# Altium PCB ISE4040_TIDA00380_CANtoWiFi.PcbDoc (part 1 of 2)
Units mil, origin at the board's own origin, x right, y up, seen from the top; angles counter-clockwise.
Board outline 2700 x 3450 mil, 4 copper layers (Top Layer, Signal Layer 1, Signal Layer 2, Bottom Layer), stack 61.6 mil thick; 119 components, 58 nets, 367 pads, 332 vias.
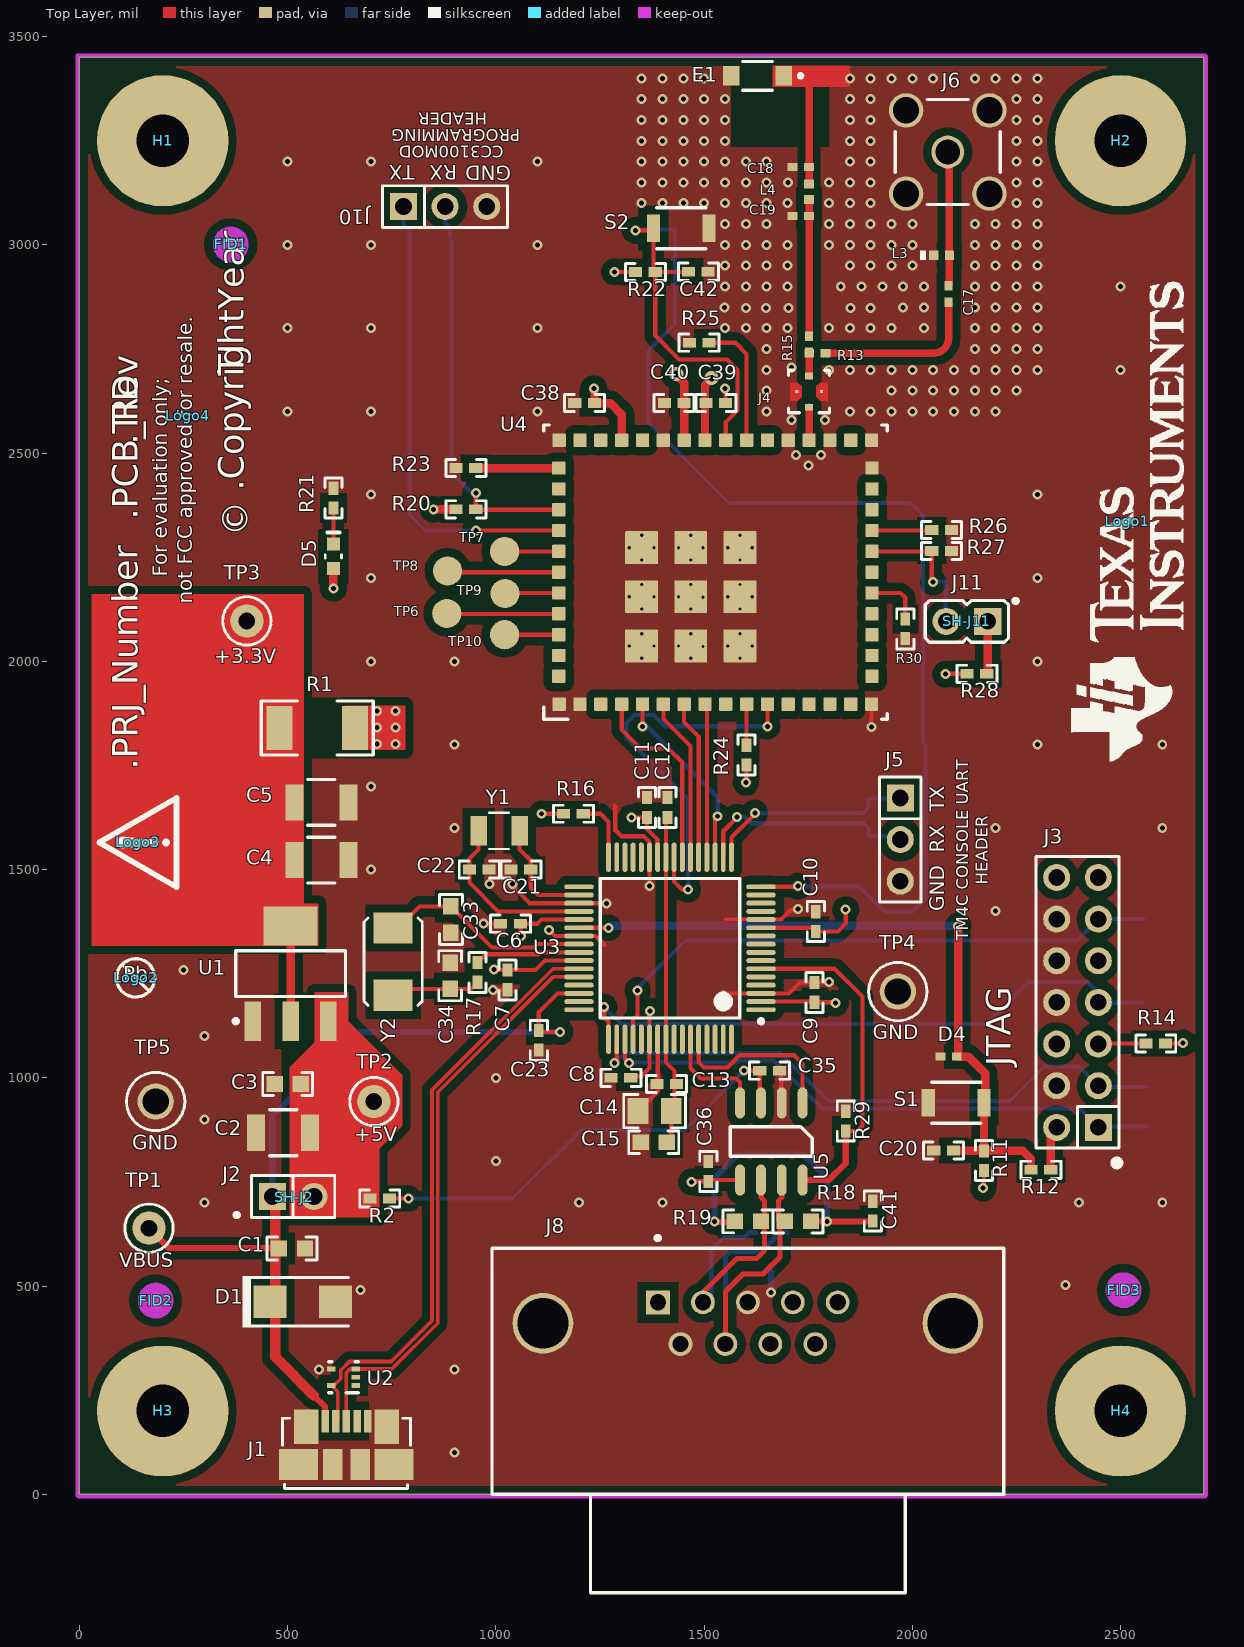
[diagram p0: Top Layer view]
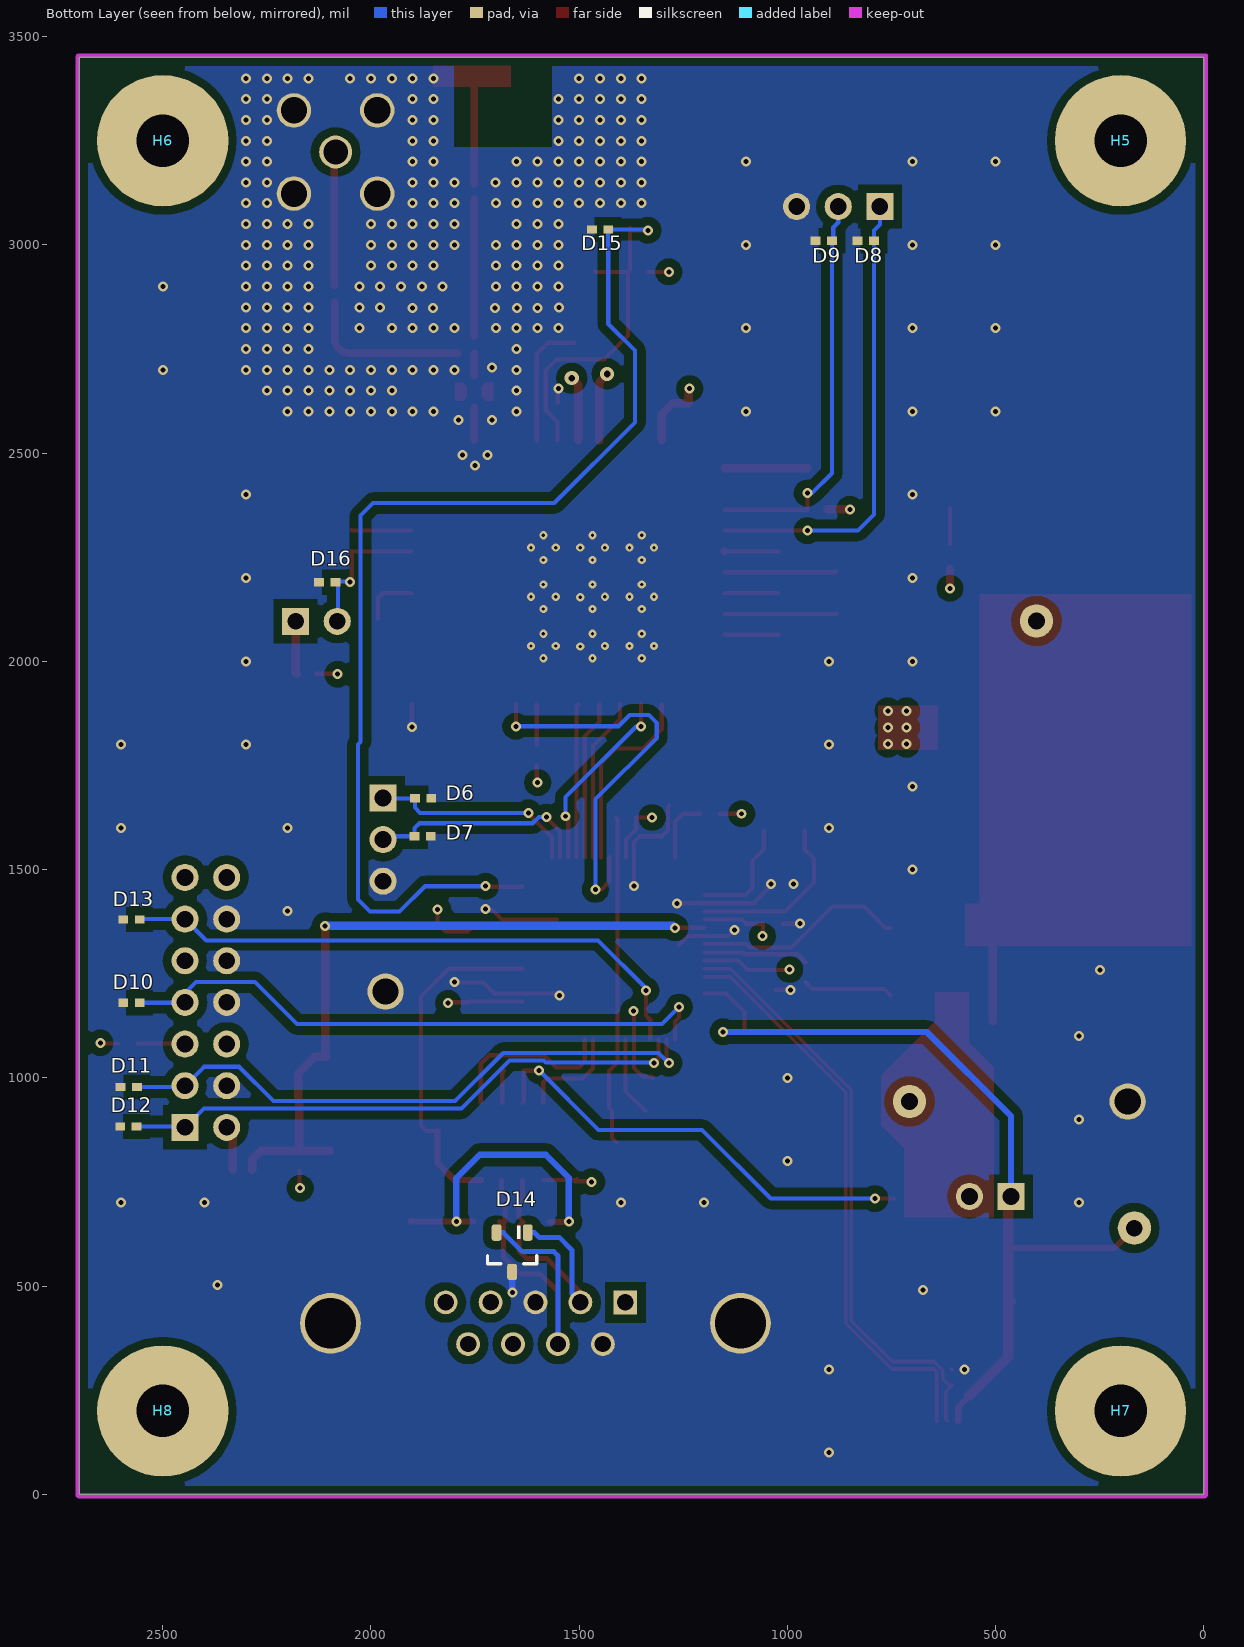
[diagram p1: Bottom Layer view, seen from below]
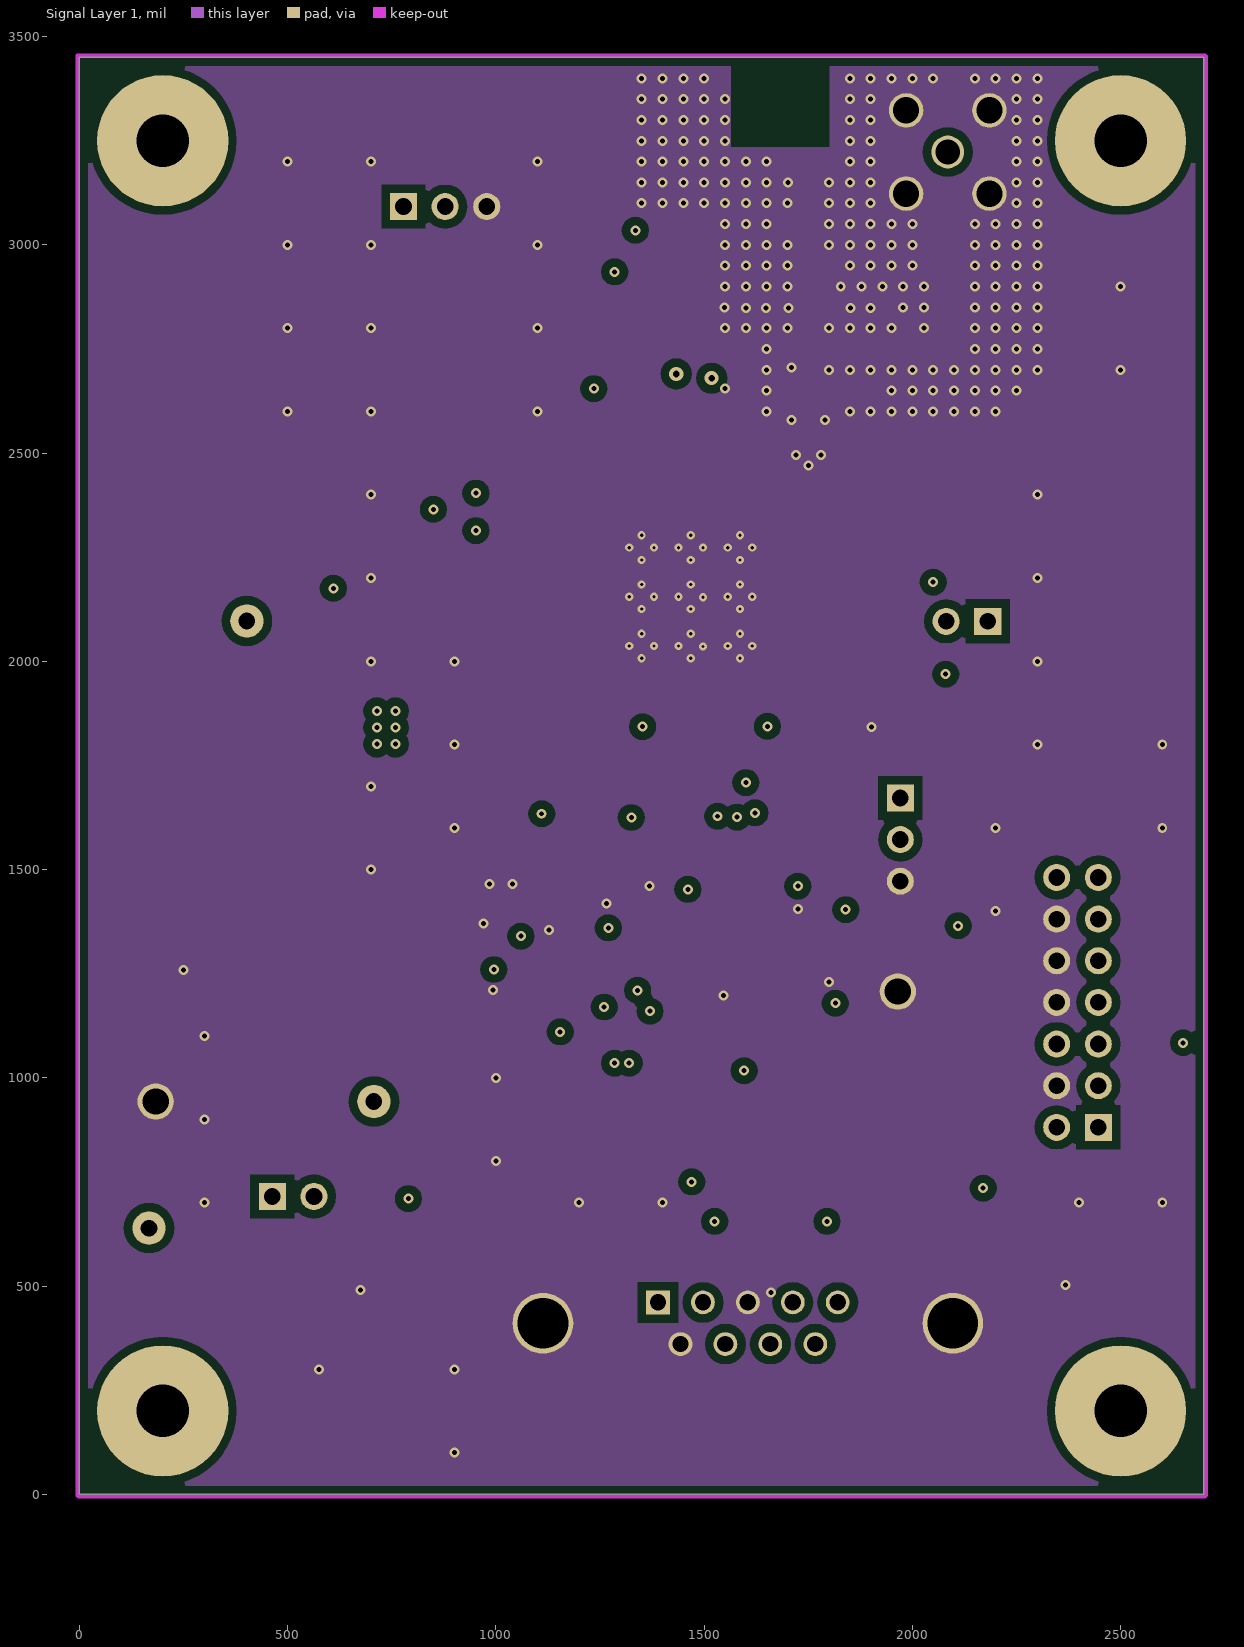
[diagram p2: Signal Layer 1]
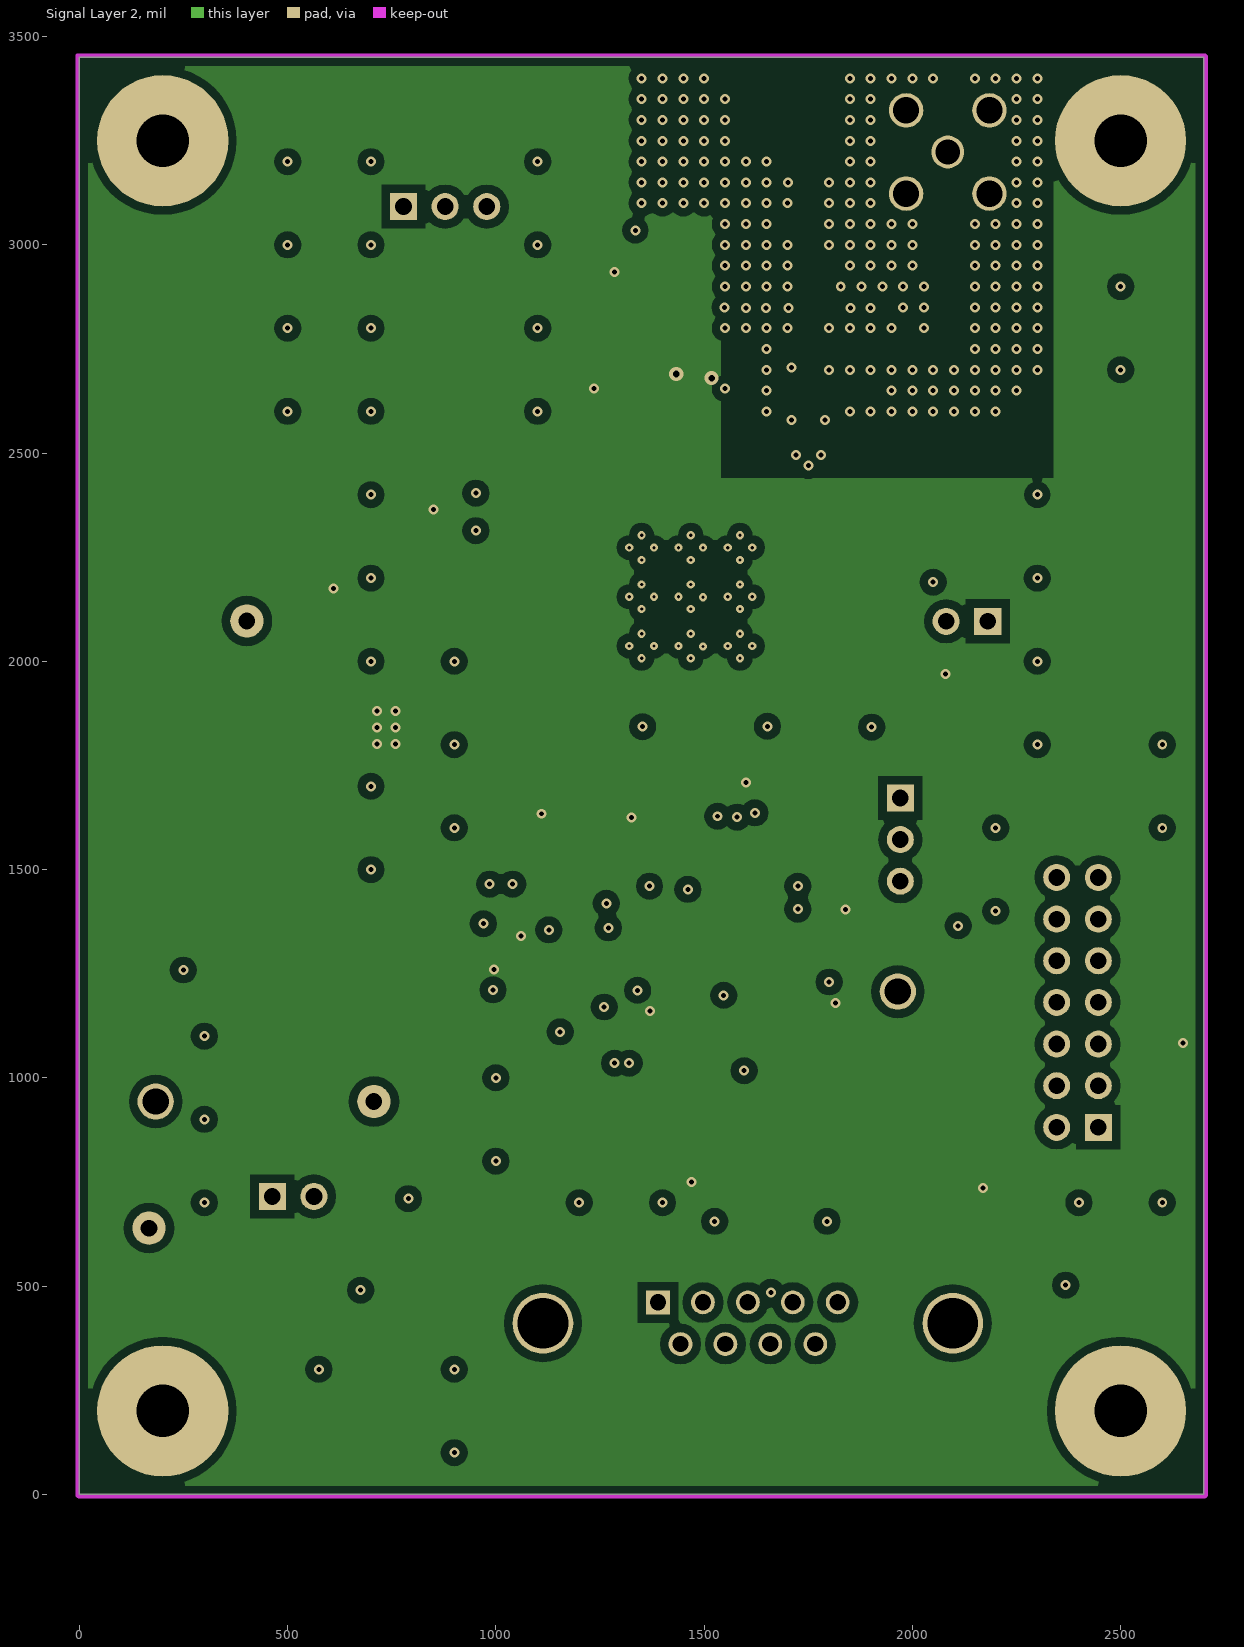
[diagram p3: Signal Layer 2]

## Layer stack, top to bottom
Top Solder: solder mask 0.4, Solder Resist, Dk 3.5
Top Layer: signal copper 1.4
Dielectric1: core 10, FR-4 High TG, Dk 4.2
Signal Layer 1: signal copper 1.4
Dielectric 3: prepreg 36, FR-4 High TG, Dk 4.2
Signal Layer 2: signal copper 1.4
Dielectric 2: core 10, FR-4 High TG, Dk 4.2
Bottom Layer: signal copper 1.4
Bottom Solder: solder mask 0.4, Solder Resist, Dk 3.5

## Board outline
0,0 0,3450 2700,3450 2700,0

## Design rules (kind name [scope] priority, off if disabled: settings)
AcuteAngle [All] p1: minimum=4.50000000000000E+0001 checktracksonly=FALSE
AssemblyTestPointUsage [All] p1: valid=2
Clearance Clearance_1 [All vs InComponent('FL1')] p1: gap=5
Clearance Clearance_Keepouts [((IsTrack Or IsArc) And Not InPoly) And IsFree and IsKeepOut vs ((IsTrack Or IsArc) And Not InPoly) And IsFree and IsKeepOut] p2: gap=0
Clearance Clearance_BoardEdge_MountingHoles [OnCopper and InComponentClass('Mounting Holes') vs IsKeepOut] p3: gap=40
Clearance Clearance_BoardEdge_Poly [OnCopper and InPoly vs IsKeepOut] p4: gap=20
Clearance Clearance_BoardEdge [OnCopper and Not InComponentClass('Logo') and not InComponentClass('FiducialMark') and not InRegion(1000,500,4000,800) and Not IsKeepout vs IsKeepOut] p5: gap=20
Clearance Clearance_Poly [InPolygon] p6: gap=20
Clearance [All] p7: gap=7.87 except(4.5: Arc-Track Track-Track; 6.8: SMDPad-SMDPad)
ComponentClearance ComponentClearance_1 [All vs InComponent('R15')] p1: gap=0 collisioncheckmode=3 verticalgap=0 showdistances=FALSE
ComponentClearance ComponentClearance_MountingHoles_FiducialMarks [InComponentClass('Mounting Holes') vs InComponentClass('FiducialMark')] p2: gap=50 collisioncheckmode=3 verticalgap=10 showdistances=FALSE
ComponentClearance ComponentClearance_Shunt [InComponentClass('Header') vs InComponentClass('Shunt')] p3: gap=0 collisioncheckmode=3 verticalgap=0 showdistances=FALSE
ComponentClearance ComponentClearance_Logo [InComponentClass('Logo')] p4: gap=50 collisioncheckmode=3 verticalgap=10 showdistances=FALSE
ComponentClearance ComponentClearance_ScrewToNut [(HasFootprint('NY PMS 440 0025 PH')) vs (HasFootprint('Keystone_1902C'))] p5: gap=5 collisioncheckmode=3 verticalgap=10 showdistances=FALSE
ComponentClearance ComponentClearance_MountingHoles [InComponentClass('Mounting Holes')] p6: gap=150 collisioncheckmode=3 verticalgap=100000 showdistances=FALSE
ComponentClearance ComponentClearance_SmallPassives [HasFootprint('0201*') or HasFootprint('0402*') or HasFootprint('0508') or HasFootprint('0603*') or HasFootprint('0612') or HasFootprint('0805*') or HasFootprint('0815*') or HasFootprint('0830*') or HasFootprint('1206*') or HasFootprint('1210*') or HasFootprint('1808*') or HasFootprint('1812*') or HasFootprint('1825*') or HasFootprint('2010*') or HasFootprint('2220*') or HasFootprint('2225*') or HasFootprint('2512*') or HasFootprint('2728*') or HasFootprint('3518*') vs HasFootprint('0201*') or HasFootprint('0402*') or HasFootprint('0508') or HasFootprint('0603*') or HasFootprint('0612') or HasFootprint('0805*') or HasFootprint('0815*') or HasFootprint('0830*') or HasFootprint('1206*') or HasFootprint('1210*') or HasFootprint('1808*') or HasFootprint('1812*') or HasFootprint('1825*') or HasFootprint('2010*') or HasFootprint('2220*') or HasFootprint('2225*') or HasFootprint('2512*') or HasFootprint('2728*') or HasFootprint('3518*')] p7: gap=20 collisioncheckmode=3 verticalgap=10 showdistances=FALSE
ComponentClearance ComponentClearance_THtoSMT [IsThruComponent vs IsSMTComponent] p8: gap=25 collisioncheckmode=3 verticalgap=30 showdistances=FALSE
ComponentClearance ComponentClearance_THtoTH [IsThruComponent vs IsThruComponent] p9: gap=100 collisioncheckmode=3 verticalgap=30 showdistances=FALSE
ComponentClearance [All] p10: gap=25 collisioncheckmode=3 verticalgap=10 showdistances=FALSE
DiffPairsRouting DiffPairsRouting_1 [(InNet('CAN_N') AND InNet('CAN_P'))] p1: maxlimit=10 minlimit=10 mostfreqgap=10 toplayer_minwidth=12 toplayer_maxwidth=12 toplayer_prefwidth=12 midlayer1_minwidth=12 midlayer1_maxwidth=12 midlayer1_prefwidth=12 midlayer2_minwidth=12 midlayer2_maxwidth=12 midlayer2_prefwidth=12 bottomlayer_minwidth=12 bottomlayer_maxwidth=12 bottomlayer_prefwidth=12 maxuncoupledlength=500
DiffPairsRouting [All] p2: maxlimit=25 minlimit=5 mostfreqgap=5 toplayer_minwidth=8.5 toplayer_maxwidth=12 toplayer_prefwidth=8.5 midlayer1_minwidth=8.5 midlayer1_maxwidth=12 midlayer1_prefwidth=8.5 midlayer2_minwidth=8.5 midlayer2_maxwidth=12 midlayer2_prefwidth=8.5 bottomlayer_minwidth=8.5 bottomlayer_maxwidth=12 bottomlayer_prefwidth=8.5 maxuncoupledlength=1000
FabricationTestPointUsage TestPointUsage [All] p1: valid=2 allowmultiple=FALSE
FabricationTestpoint Testpoint [All] p1: side=3 testpointundercomponent=TRUE minsize=40 maxsize=100 preferedsize=60 minholesize=0 maxholesize=40 preferedholesize=32 testpointgrid=1 allowsidetop=TRUE allowsidebottom=TRUE usegrid=TRUE gridtolerance=0.01
FanoutControl Fanout_LCC [IsLCC] p1: bgadir=Out bgaviamode=Centered fanoutstyle=Auto fanoutdirection=Alternating viagrid=1 // Fanout_LCC (Default Rule)
FanoutControl Fanout_BGA [IsBGA] p2: bgadir=Out bgaviamode=Centered fanoutstyle=Auto fanoutdirection=Alternating viagrid=1 // Fanout_BGA (Default Rule)
FanoutControl Fanout_Default [All] p4: bgadir=Out bgaviamode=Centered fanoutstyle=Auto fanoutdirection=Alternating viagrid=1 // Fanout_Default (Default Rule)
FanoutControl Fanout_Small [(CompPinCount < 5)] p5: bgadir=Out bgaviamode=Centered fanoutstyle=Auto fanoutdirection=OutThenIn viagrid=1 // Fanout_Small (Default Rule)
HoleSize [All] p1: absolutevalues=TRUE maxlimit=251 minlimit=5 maxpercent=80.000 minpercent=20.000
MinimumAnnularRing MinimumAnnularRing_ThermalPadVias [IsVia and InAnyComponent] p1: minimumring=5.91
MinimumAnnularRing [All] p2: minimumring=5
MinimumSolderMaskSliver MinimumSolderMaskSliver_Logo [InComponentClass('Logo') vs InComponentClass('Logo')] p1: minsoldermaskwidth=0.7
MinimumSolderMaskSliver [All] p2: minsoldermaskwidth=3.4
PlaneConnect [All] p1: planeconnectstyle=Direct reliefexpansion=10 reliefentries=4 reliefconductorwidth=10 reliefairgap=10
PolygonConnect [All] p1: connectstyle=Direct reliefconductorwidth=10 reliefentries=4 polygonreliefangle="90 Angle" airgapwidth=10
RoutingVias ThermalPadVias [IsVia and InAnyComponent] p1: holewidth=7.87 width=19.68 viastyle="Through Hole" minholewidth=7.87 minwidth=19.68 maxholewidth=12.99 maxwidth=23.62
RoutingVias [All] p2: holewidth=16 width=34 viastyle="Through Hole" minholewidth=5 minwidth=20 maxholewidth=40 maxwidth=65
SilkToBoardRegionClearance [Not ((IsComment or IsDesignator) And (Hide <> 'False')) and not InRegion(1000,500,4000,800)] p1:
SilkToSilkClearance SilkToSilkClearance_Pb-FreeLogo [(HasFootprint('Pb-Free_Overlay_Medium') OR HasFootprint('Pb-Free_Overlay_Small')) vs (HasFootprint('Pb-Free_Overlay_Medium') OR HasFootprint('Pb-Free_Overlay_Small'))] p1: silktosilkclearance=0
SilkToSilkClearance [All] p2: silktosilkclearance=5
SilkToSolderMaskClearance "Silk to Solder Mask Opening" [All] p1 off: minsilkscreentomaskgap=1 clearancetoexposedcopper=FALSE
SolderMaskExpansion [All] p1: expansion=1.97
UnpouredPolygon [All] p1: allowunpoured=FALSE
Width "Schematic Width Constraint_1" [InNet('3V3')] p1: maxlimit=100 minlimit=5 preferedwidth=25
Width "Schematic Width Constraint_3" [InNet('3V3_OUT')] p2: maxlimit=100 minlimit=5 preferedwidth=25
Width "Schematic Width Constraint_2" [InNet('5V')] p3: maxlimit=100 minlimit=5 preferedwidth=25
Width "Schematic Width Constraint" [InNet('VBUS')] p4: maxlimit=100 minlimit=5 preferedwidth=25
Width [All] p5: maxlimit=100 minlimit=6 preferedwidth=10 checkconnectedcopper=TRUE
14 further rules are at their usual default settings.

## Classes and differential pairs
component class "Mounting Holes": H1 H2 H3 H4
component class Logo: Logo1
component class ISE4040_TIDA00380_CANtoWiFi_Sheet5: FID1 FID2 FID3 H1 H2 H3 H4 H5 H6 H7 H8 Logo1 Logo2 Logo3 Logo4 ZZ1 ZZ2 ZZ3 ZZ4
component class FiducialMark: FID1 FID2 FID3
component class AssemblyNote: ZZ1 ZZ2 ZZ3 ZZ4
component class Header: J2 J3 J5 J10 J11
component class ISE4040_TIDA00380_CANtoWiFi_Sheet2: C1 C2 C3 C4 C5 D1 D5 J1 J2 R1 R21 SH-J2 TP1 TP2 TP3 TP4 TP5 U1 U2
component class ISE4040_TIDA00380_CANtoWiFi_Sheet3: C6 C7 C8 C9 C10 C11 C12 C13 C14 C15 C20 C21 C22 C23 C33 C34 C35 C36 C41 D4 D6 D7 D10 D11 D12 D13 D14 J3 J5 J8 R2 R11 R12 R14 R16 R17 R18 R19 R29 S1 SH-J1 U3 U5 Y1 Y2
component class ISE4040_TIDA00380_CANtoWiFi_Sheet4: C17 C18 C19 C38 C39 C40 C42 D8 D9 D15 D16 E1 J4 J6 J10 J11 L3 L4 R13 R15 R20 R22 R23 R24 R25 R26 R27 R28 R30 S2 SH-J11 TP6 TP7 TP8 TP9 TP10 U4
component class Shunt: SH-J2 SH-J11
net class "50 OHM": ANT_LEG CC_RF_OUT RF_FL_O SMA_LEG SMA_OUT
differential pair CAN: +CAN_P -CAN_N
differential pair USB_D: +USB_D_P -USB_D_N

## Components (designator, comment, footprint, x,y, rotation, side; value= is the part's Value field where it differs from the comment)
C1 "06033C104JAT2A" 0603 510,590 r0 top
C2 "C1210C107M8PACTU" 1210_280 489,868 r180 top
C3 "06033C104JAT2A" 0603 500,985 r180 top
C4 "C1210C107M8PACTU" 1210_280 580.9,1522.6 r0 top
C5 "C1210C107M8PACTU" 1210_280 580.9,1661.3 r0 top
C6 "GRM155R71C104KA88D" 0402 1035,1370 r180 top
C7 "GRM155R71C104KA88D" 0402 1028,1235 r270 top
C8 "GRM155R71C104KA88D" 0402 1300,1000 r180 top
C9 "GRM155R71C104KA88D" 0402 1765,1205 r90 top
C10 "GRM155R71C104KA88D" 0402 1768,1375 r90 top
C11 "GRM155R71C104KA88D" 0402 1363,1649 r90 top
C12 "GRM155R71C104KA88D" 0402 1412,1649 r90 top
C13 "GRM155R71C104KA88D" 0402 1410,985 r180 top
C14 "C0805C225K8RACTU" 0805_HV 1381,920 r180 top
C15 "GRM188R71C105KA12D" 0603 1379,845 r180 top
C17 "GRM1555C1H100JA01D" 0402L 2087,2882 r270 top
C18 "GRM1555C1H1R0BA01D" 0402L 1732,3187 r180 top locked
C19 "GRM1555C1H1R0BA01D" 0402L 1732,3069 r180 top
C20 "GRM155R71C104KA88D" 0402 2075,825 r180 top
C21 "GRM1555C1H240JA01D" 0402 1060,1500 r0 top
C22 "GRM1555C1H240JA01D" 0402 960,1500 r180 top
C23 "GRM155R71C104KA88D" 0402 1103,1090 r270 top
C33 "GRM1885C1H200JA01D" 0603 892,1380 r270 top
C34 "GRM1885C1H200JA01D" 0603 890,1245 r90 top
C35 "GRM155R71C104KA88D" 0402 1657,1017 r0 top
C36 "GRM155R71C104KA88D" 0402 1510,775 r90 top
C38 "GRM155R60J475ME87D" 0402 1213,2620 r180 top
C39 "GRM155R71C104KA88D" 0402 1528,2620 r0 top
C40 "GRM155R60J475ME87D" 0402 1428,2620 r180 top
C41 "C1005X7R1E472K" 0402 1905,680 r90 top
C42 "GRM155R71C104KA88D" 0402 1486,2935.5 r0 top
D1 "SMAJ5.0CA" SMA 536,462 r0 top
D4 "TPD1E10B06DPYR" DPY0002A 2087,1050.81 r180 top
D5 "LG L29K-G2J1-24-Z" "LG L29K_GREEN" 609.68,2252 r90 top
D6 "TPD1E10B06DPYR" DPY0002A 1875,1671 r180 bottom
D7 "TPD1E10B06DPYR" DPY0002A 1876,1580 r180 bottom
D8 "TPD1E10B06DPYR" DPY0002A 812,3010 r0 bottom
D9 "TPD1E10B06DPYR" DPY0002A 913,3010 r0 bottom
D10 "TPD1E10B06DPYR" DPY0002A 2575,1180 r0 bottom
D11 "TPD1E10B06DPYR" DPY0002A 2581.5,978 r0 bottom
D12 "TPD1E10B06DPYR" DPY0002A 2582.5,883 r0 bottom
D13 "TPD1E10B06DPYR" DPY0002A 2575,1380 r0 bottom
D14 "NUP2105LT1G" SOT-23 1661,581 r270 bottom
D15 "TPD1E10B06DPYR" DPY0002A 1450,3037 r0 bottom
D16 "TPD1E10B06DPYR" DPY0002A 2105,2190 r0 bottom
E1 "AH316M245001-T" TAYO_AH316M 1628,3406 r180 top locked
FID1 "Fiducial" Fiducial10-20 363.36,3000.93 r0 top
FID2 "Fiducial" Fiducial10-20 183,465 r0 top
FID3 "Fiducial" Fiducial10-20 2507,490 r0 top
H1 "NY PMS 440 0025 PH" "NY PMS 440 0025 PH" 200,3250 r0 top locked
H2 "NY PMS 440 0025 PH" "NY PMS 440 0025 PH" 2500,3250 r0 top locked
H3 "NY PMS 440 0025 PH" "NY PMS 440 0025 PH" 200,200 r0 top locked
H4 "NY PMS 440 0025 PH" "NY PMS 440 0025 PH" 2500,200 r0 top locked
H5 "1902C" Keystone_1902C 200,3250 r180 bottom locked
H6 "1902C" Keystone_1902C 2500,3250 r180 bottom locked
H7 "1902C" Keystone_1902C 200,200 r180 bottom locked
H8 "1902C" Keystone_1902C 2500,200 r180 bottom locked
J1 "0473460001" CONN_47346-0001 641,14 r180 top
J2 "90120-0122" CONN_90120-0122 513,715 r0 top
J3 "PEC07DAAN" CONN_PEC07DAAN 2396.5,1181 r90 top
J4 "MM8030-2610RJ3" MuRata_MM8030-2610 1752,2647.8 r90 top
J5 "PBC03SAAN" PBC03SAAN 1971,1572 r270 top
J6 "5-1814832-1" TE_5-1814832-1 2085,3223 r90 top
J8 "9651627813" "Harting_09 65 162 6810" 1605,0 r0 top
J10 "PBC03SAAN" PBC03SAAN 878,3092 r0 top
J11 "PBC02SAAN" Sullins_PBC02SAAN 2131,2096 r270 top
L3 "LQG15HS3N6S02D" IND_LQG15H 2070,2975 r0 top
L4 "LQP15MN3N6B02D" LQP_0402 1752,3128 r90 top
Logo1 "Texas Instruments" TI_Stacked_Overlay_Medium 2516,2336 r90 top
Logo2 "Pb-Free Symbol" Pb-Free_Overlay_Small 135,1240 r0 top
Logo3 "CAUTION.  READ USER GUIDE BEFORE USE" IEC_Caution_Small 140,1565 r90 top
Logo4 "FCC disclaimer" FCC_disclaimer_stacked 260,2590 r270 top
R1 "CRCW20100000Z0EF" 2010 571,1840 r0 top
R2 "CRCW04020000Z0ED" 0402 721,710 r180 top
R11 "CRCW040210K0FKED" 0402 2172,801 r270 top
R12 "CRCW04020000Z0ED" 0402 2308.5,779 r0 top
R13 "CRCW04020000Z0ED" 0402L 1772,2740 r0 top
R14 "CRCW04020000Z0ED" 0402 2584.5,1082 r0 top
R15 "CRCW04020000Z0ED" 0402L 1752,2761 r270 top
R16 "CRCW0402200KFKED" 0402 1186,1634 r0 top
R17 "CRCW04020000Z0ED" 0402 956,1253 r90 top
R18 "CRCW060360R4FKEA" 0603 1725,655 r180 top
R19 "CRCW060360R4FKEA" 0603 1605,655 r0 top
R20 "CRCW0402100KFKED" 0402 928,2365 r180 top
R21 "CRCW0402402RFKED" 0402 609.68,2392 r270 top
R22 "CRCW0402100KFKED" 0402 1359,2935 r180 top
R23 "CRCW0402100KFKED" 0402 928,2464 r0 top
R24 "CRCW0402100KFKED" 0402 1602,1775 r270 top
R25 "CRCW0402100KFKED" 0402 1488,2765 r0 top
R26 "CRCW0402100KFKED" 0402 2070,2315 r180 top
R27 "CRCW04022K67FKED" 0402 2070,2265 r180 top
R28 "CRCW0402270RJNED" 0402 2155,1970 r180 top
R29 "CRCW0402100KFKED" 0402 1840,896 r270 top
R30 "CRCW0402100KFKED" 0402 1983,2078 r90 top
S1 "B3U-1000P" SW_B3U-1000P 2105,940 r180 top
S2 "B3U-1000P" SW_B3U-1000P 1445,3040 r0 top
SH-J2 "2SN-BK-G" 2SN-BK-G 516,713 r180 top
SH-J11 "2SN-BK-G" 2SN-BK-G 2131,2096 r180 top
TP1 "5000" Keystone5000 167,639 r0 top
TP2 "5000" Keystone5000 707,943 r0 top
TP3 "5000" Keystone5000 402,2097 r0 top
TP4 "5128" Keystone5128 1965,1207 r0 top
TP5 "5128" Keystone5128 183.03,943 r0 top
TP6 "Pogo Pad" PogoPad 882,2115 r0 top
TP7 "Pogo Pad" PogoPad 1021,2264 r0 top
TP8 "Pogo Pad" PogoPad 884,2217 r0 top
TP9 "Pogo Pad" PogoPad 1022,2163 r0 top
TP10 "Pogo Pad" PogoPad 1021,2064 r90 top
U1 "TLV1117LV33DCYR" DCY0004A_N 507,1250.12 r90 top
U2 "TPD2E2U06DRL" DRL0005A 634,281 r180 top
U3 "TM4C123GH6PMI7R" PM0064A_N 1418,1311 r180 top
U4 "CC3100MODR11MAMOBR" MOB0063A 1527,2214 r90 top
U5 "SN65HVD256D" D0008A_L 1661.35,847 r270 top
Y1 "NX3215SA-32.768K-STD-MUA-8" XTAL_NX3215SA 1007.65,1593.15 r180 top
Y2 "ABM3-16.000MHZ-D2Y-T" XTAL_ABM3 753,1279 r90 top
ZZ1 "These assemblies are ESD sensitive, ESD precautions shall be observed." AssemblyNote 185,3939.11 r0 top
ZZ2 "These assemblies must be clean and free from flux and all contaminants. Use of no clean flux is not acceptable." AssemblyNote 185,3850.56 r0 top
ZZ3 "These assemblies must comply with workmanship standards IPC-A-610 Class 2, unless otherwise specified." AssemblyNote 185,3762 r0 top
ZZ4 "Place SH-J2 on J2, SH-J11 on J11" AssemblyNote 180,3680 r0 top

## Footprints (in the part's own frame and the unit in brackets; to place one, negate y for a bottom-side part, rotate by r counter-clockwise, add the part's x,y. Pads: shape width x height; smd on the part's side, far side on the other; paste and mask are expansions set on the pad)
2SN-BK-G [mil] "Samtec STEP model"
  round 1 on Mech3: 0(0,0)
  body extent -78,-39 79,39, height 188
0402 [mm] "0402 from SM-752 data"
  rect 0.8x0.6 smd: 1(-0.6,0) 2(0.6,0)
  silkscreen extent -1.22,-0.52 1.22,0.52, body extent -0.55,-0.3 0.55,0.3, height 0.6
0402L [mm] "0402 from SM-752 data"
  rect 0.6x0.5 smd: 1(-0.5,0) 2(0.5,0)
  body extent -0.55,-0.3 0.55,0.3, height 0.6
0603 [mm] "0603 from SM-752 data"
  rect 1x0.95 smd: 1(-0.8,0) 2(0.8,0)
  silkscreen extent -1.52,-0.69 1.52,0.69, body extent -0.87,-0.47 0.87,0.47, height 0.85
0805_HV [mil] "0805 with 30mil clearance between pads"
  rect 50x63 smd: 1(-40,0) 2(40,0)
  silkscreen extent -74,-40 74,40, body extent -43,-29 43,29, height 43
1210_280 [mm] "SMD, 2-Leads, Body 3.6x2.8mm, Height 2.8mm"
  rect 1.1x2.2 smd: 1(-1.65,0) 2(1.65,0)
  silkscreen extent -0.84,-1.4 0.84,1.4, body extent -1.8,-1.4 1.8,1.4, height 2.8
2010 [mm] "Chip Capacitor, Body 5.08x2.54mm, IPC Medium Density"
  rect 1.6x2.7 smd: 1(-2.3,0) 2(2.3,0)
  silkscreen extent -3.42,-1.65 3.42,1.65, body extent -2.73,-1.45 2.73,1.45, height 1.66
AssemblyNote [mil] "Assembly Note"
CONN_47346-0001 [mm] "MOLEX"
  rect 0.45x1.38 smd mask+0.043: 1(1.3,-4.105) 2(0.65,-4.105) 3(0,-4.105) 4(-0.65,-4.105) 5(-1.3,-4.105)
  rect 1.5x2.1 smd mask+0.043: 6(-2.45,-3.755) 11(2.45,-3.75)
  rect 2.375x1.9 smd mask+0.043: 7(-2.912,-1.45) 10(2.912,-1.45)
  rect 1.175x1.9 smd mask+0.043: 8(-0.837,-1.45) 9(0.837,-1.45)
  silkscreen extent -3.9,-4.28 3.9,0, body extent -3.99,-4.43 3.99,1, height 2.72
CONN_90120-0122 [mm] "Molex"
  rect 1.65x1.65 hole 1.016 mask+0: 1(-1.27,0)
  round 1.65 hole 1.016 mask+0: 2(1.27,0)
  silkscreen extent -3.56,-1.27 2.54,1.27, body extent -2.54,-1.27 2.54,1.27, height 9.29
CONN_PEC07DAAN [mm] "SULLINS"
  rect 1.65x1.65 hole 1.016 mask+0: 1(-7.62,-1.27)
  round 1.65 hole 1.016 mask+0: 2(-7.62,1.27) 3(-5.08,-1.27) 4(-5.08,1.27) 5(-2.54,-1.27) 6(-2.54,1.27) 7(0,-1.27) 8(0,1.27) 9(2.54,-1.27) 10(2.54,1.27) 11(5.08,-1.27) 12(5.08,1.27) 13(7.62,-1.27) 14(7.62,1.27)
  silkscreen extent -9.99,-2.6 8.89,2.54, body extent -8.95,-2.6 8.95,2.6, height 11.43
D0008A_L [mm] "SOIC, 8-Leads, Body 4.9x3.9mm, Pitch 1.27mm, IPC High Density"
  oval 1.9x0.6 smd: 1(-2.35,1.905) 2(-2.35,0.635) 3(-2.35,-0.635) 4(-2.35,-1.905) 5(2.35,-1.905) 6(2.35,-0.635) 7(2.35,0.635) 8(2.35,1.905)
  silkscreen extent -0.9,-2.5 0.9,2.5, body extent -3,-2.45 3,2.45, height 1.63
DCY0004A_N [mm] "SOT223/SC73, 4-Leads, Body 6.5x3.5mm, Pitch 2.3mm, Lead Span 7mm, IPC Medium Density"
  rect 2.4x1 smd: 1(-2.9,2.3) 2(-2.9,0) 3(-2.9,-2.3)
  rect 2.4x3.3 smd: 4(2.9,0)
  silkscreen extent -3.02,-3.35 1.4,3.47, body extent -3.5,-3.25 3.5,3.25, height 1.62
DPY0002A [mm] "R-PX2SON-N2"
  rect 0.6x0.5 smd: 1(-0.5,0) 2(0.5,0)
  body extent -0.55,-0.35 0.55,0.35, height 0.4
DRL0005A [mm] "SOTFL, 5-Flat Leads, Body 1.2x1.6x0.6mm, Pitch 0.5mm, TI recommended"
  rect 0.5x0.3 smd: 1(-0.75,0.5) 2(-0.75,0) 3(-0.75,-0.5) 4(0.75,-0.5) 5(0.75,0.5)
  silkscreen extent -0.9,-0.95 0.9,0.95, body extent -0.85,-0.85 0.85,0.85, height 0.62
FCC_disclaimer_stacked [mil]
Fiducial10-20 [mm]
  round 1 smd mask+0.5: 1(0,0)
  Top Layer keep-out circle w1.178: c0,0 r0.5
"Harting_09 65 162 6810" [mm] "Harting"
  rect 1.45x1.45 hole 1 paste+0: 1(-5.48,11.7)
  round 1.45 hole 1 paste+0: 2(-2.74,11.7) 3(0,11.7) 4(2.74,11.7) 5(5.48,11.7) 6(-4.11,9.16) 7(-1.37,9.16) 8(1.37,9.16) 9(4.11,9.16)
  round 3.7 hole 3.1 paste+0: 10(-12.5,10.43) 11(12.5,10.43)
  silkscreen extent -15.6,-6 15.6,15.75, body extent -15.6,-6 15.6,15, height 13.6
IEC_Caution_Small [mil]
  silkscreen extent -107,-93 107,92
IND_LQG15H [mm] "MuRata"
  rect 0.55x0.6 smd: 1(-0.475,0) 2(0.475,0)
  silkscreen extent -1.3,-0.3 -0.95,0.3, body extent -0.52,-0.27 0.52,0.27, height 0.55
Keystone5000 [mil] "For Keystone 500x miniature loop terminals"
  round 80 hole 40: 1(0,0)
  silkscreen extent -58,-58 58,58, body extent -49,-49 49,49, height 182
Keystone5128 [mil] "Keystone Multipurpose loops"
  round 87 hole 63: 1(0,0)
  silkscreen extent -70,-70 70,70, body extent -63,-63 63,62, height 319
Keystone_1902C [mil] "Hex Standoff, 4-40 threaded, nylon"
  body extent -145,-126 146,126, height 501
"LG L29K_GREEN" [mm] "OSRAM"
  rect 0.8x0.8 smd paste-0.4: 1(-0.75,0) 2(0.75,0)
  silkscreen extent -0.1,-0.5 1.45,0.5, body extent -0.9,-0.45 0.9,0.45, height 0.67
LQP_0402 [mm] "SMD, 2-Leads, Body 1.1x0.6mm"
  rect 0.55x0.6 smd: 1(-0.475,0) 2(0.475,0)
  body extent -0.55,-0.3 0.55,0.3, height 0.45
MOB0063A [mm]
  rrect12% 0.81x0.81 smd: 1(-8.05,9.525) 2(-8.05,8.255) 3(-8.05,6.985) 4(-8.05,5.715) 5(-8.05,4.445) 6(-8.05,3.175) 7(-8.05,1.905) 8(-8.05,0.635) 9(-8.05,-0.635) 10(-8.05,-1.905) 11(-8.05,-3.175) 12(-8.05,-4.445) 13(-8.05,-5.715) 14(-8.05,-6.985) 15(-8.05,-8.255) 16(-8.05,-9.525) 17(-6.35,-9.55) 18(-5.08,-9.55) 19(-3.81,-9.55) 20(-2.54,-9.55) 21(-1.27,-9.55) 22(0,-9.55) 23(1.27,-9.55) 24(2.54,-9.55) 25(3.81,-9.55) 26(5.08,-9.55) 27(6.35,-9.55) 28(8.05,-9.525) 29(8.05,-8.255) 30(8.05,-6.985) 31(8.05,-5.715) 32(8.05,-4.445) 33(8.05,-3.175) 34(8.05,-1.905) 35(8.05,-0.635) 36(8.05,0.635) 37(8.05,1.905) 38(8.05,3.175) 39(8.05,4.445) 40(8.05,5.715) 41(8.05,6.985) 42(8.05,8.255) 43(8.05,9.525) 44(6.35,9.55) 45(5.08,9.55) 46(3.81,9.55) 47(2.54,9.55) 48(1.27,9.55) 49(0,9.55) 50(-1.27,9.55) 51(-2.54,9.55) 52(-3.81,9.55) 53(-5.08,9.55) 54(-6.35,9.55)
  rrect5% 2x2 smd paste-1: 55(-4.5,4.5) 56(-4.5,1.5) 57(-4.5,-1.5) 58(-1.5,4.5) 59(-1.5,1.5) 60(-1.5,-1.5) 61(1.5,4.5) 62(1.5,1.5) 63(1.5,-1.5)
  silkscreen extent -8.97,-10.48 8.98,10.48, body extent -8.87,-10.37 8.87,10.37, height 2.46
MuRata_MM8030-2610 [mm] "Coaxial Connectors with Switch, SMD"
  rect 0.4x0.5 smd paste-0.5: 1(-0.95,0) 2(0.95,0)
  rect 0.2x0.2 smd paste-0.2: 3(0,0.75) 4(0,-0.75)
  Top Layer region: -0.32,0.45 -0.55,0.68 -0.55,1.15 0.55,1.15 0.55,0.68 0.32,0.45
  Top Layer region: -0.32,-0.45 -0.55,-0.68 -0.55,-1.15 0.55,-1.15 0.55,-0.68 0.32,-0.45
  silkscreen extent -1.3,-1.25 1.3,1.25, body extent -1.15,-1.1 1.15,1.1, height 1
"NY PMS 440 0025 PH" [mm] "4-40 nylon screw and mounting hole"
  round 8 hole 3.2: 1(0,0)
  body extent -3.3,-3.3 3.3,3.3, height 2.69
Pb-Free_Overlay_Small [mil]
  silkscreen extent -46,-46 46,46
PBC03SAAN [mm] "Sullins 100mil, 1x3, 230 mil above insulator"
  rect 1.65x1.65 hole 1.016: 1(-2.54,0)
  round 1.65 hole 1.016: 2(0,0) 3(2.54,0)
  silkscreen extent -3.81,-1.27 3.81,1.27, body extent -3.81,-1.27 3.81,1.27, height 8.38
PM0064A_N [mm] "Thin QFP, 64-Leads, Body 10x10mm, Pitch 0.5mm, IPC Medium Density"
  oval 1.8x0.3 smd: 1(-5.55,3.75) 2(-5.55,3.25) 3(-5.55,2.75) 4(-5.55,2.25) 5(-5.55,1.75) 6(-5.55,1.25) 7(-5.55,0.75) 8(-5.55,0.25) 9(-5.55,-0.25) 10(-5.55,-0.75) 11(-5.55,-1.25) 12(-5.55,-1.75) 13(-5.55,-2.25) 14(-5.55,-2.75) 15(-5.55,-3.25) 16(-5.55,-3.75) 33(5.55,-3.75) 34(5.55,-3.25) 35(5.55,-2.75) 36(5.55,-2.25) 37(5.55,-1.75) 38(5.55,-1.25) 39(5.55,-0.75) 40(5.55,-0.25) 41(5.55,0.25) 42(5.55,0.75) 43(5.55,1.25) 44(5.55,1.75) 45(5.55,2.25) 46(5.55,2.75) 47(5.55,3.25) 48(5.55,3.75)
  oval 0.3x1.8 smd: 17(-3.75,-5.55) 18(-3.25,-5.55) 19(-2.75,-5.55) 20(-2.25,-5.55) 21(-1.75,-5.55) 22(-1.25,-5.55) 23(-0.75,-5.55) 24(-0.25,-5.55) 25(0.25,-5.55) 26(0.75,-5.55) 27(1.25,-5.55) 28(1.75,-5.55) 29(2.25,-5.55) 30(2.75,-5.55) 31(3.25,-5.55) 32(3.75,-5.55) 49(3.75,5.55) 50(3.25,5.55) 51(2.75,5.55) 52(2.25,5.55) 53(1.75,5.55) 54(1.25,5.55) 55(0.75,5.55) 56(0.25,5.55) 57(-0.25,5.55) 58(-0.75,5.55) 59(-1.25,5.55) 60(-1.75,5.55) 61(-2.25,5.55) 62(-2.75,5.55) 63(-3.25,5.55) 64(-3.75,5.55)
  silkscreen extent -5.68,-4.25 4.25,4.57, body extent -5,-5 5,5, height 1.61
PogoPad [mil] "No Solder Paste"
  round 70 smd paste-35: 1(0,0)
SMA [mm] "Molded Diode, 2-Leads, Body 4.3x2.6mm, IPC Medium Density, based on OnSemi component dimensions and land pattern"
  rect 2x2 smd: 1(-2,0) 2(2,0)
  silkscreen extent -3.66,-1.57 2.79,1.57, body extent -2.6,-1.3 2.6,1.3, height 2.42
SOT-23 [mm] "SOT23, 3-Leads, Body 2.9x1.3mm, Pitch 0.95mm, Lead Span 2.5mm, IPC Medium Density"
  rrect50% 1x0.6 smd: 1(-1.2,0.95) 2(-1.2,-0.95) 3(1.2,0)
  silkscreen extent -1.62,-1.5 0.7,1.5, body extent -1.16,-1.45 1.21,1.45, height 1
Sullins_PBC02SAAN [mm] "Sullins 100mil, 1x2, 230 mil above insulator"
  rect 1.65x1.65 hole 1.016: 1(0,1.27)
  round 1.65 hole 1.016: 2(0,-1.27)
  silkscreen extent -1.37,-2.54 1.27,3.1, body extent -1.27,-2.54 1.27,2.54, height 8.38
SW_B3U-1000P [mm] "OMRON"
  rect 0.8x1.7 smd: 1(-1.7,0) 2(1.7,0)
  silkscreen extent -1.5,-1.25 1.5,1.25, body extent -1.5,-1.25 1.5,1.25, height 1.75
TAYO_AH316M [mm] "SMD, 2-Leads, Body 3.2x1.6mm"
  rect 1x1.2 smd: 1(-1.6,0) 2(1.6,0)
  silkscreen extent -2.73,-0.87 0.9,0.87, body extent -1.68,-0.87 1.68,0.87, height 0.61
TE_5-1814832-1 [mm] "SMA Straight PCB Socket Die Cast, TH"
  round 2 hole 1.5: 1(0,0)
  round 2.1 hole 1.6: 2(-2.54,2.54) 3(-2.54,-2.54) 4(2.54,-2.54) 5(2.54,2.54)
  silkscreen extent -3.2,-3.2 3.2,3.2, body extent -3.2,-3.2 3.2,3.2, height 9.5
TI_Stacked_Overlay_Medium [mil]
  silkscreen extent -576,-136 576,134
XTAL_ABM3 [mm] "Abracon recommended land pattern 12.28.10"
  rect 1.9x2.4 smd: 1(-2.05,0) 2(2.05,0)
  silkscreen extent -2.67,-1.78 2.67,1.78, body extent -2.6,-1.7 2.6,1.7, height 1.3
XTAL_NX3215SA [mm] "NDK recommended land pattern"
  rect 1x1.8 smd: 1(-1.25,0) 2(1.25,0)
  silkscreen extent -0.6,-1.1 0.6,1.1, body extent -1.65,-0.8 1.65,0.8, height 0.9

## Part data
C1 C3: "CAP, CERM, 0.1 µF, 25 V, +/- 5%, X7R, 0603"
C2 C4 C5: "CAP, CERM, 100 µF, 10 V, +/- 20%, X5R, 1210"
C6 C7 C8 C9 C10 C11 C12 C13 C20 C23 C35 C36 C39 C42: "CAP, CERM, 0.1 µF, 16 V, +/- 10%, X7R, 0402"
C14: "CAP, CERM, 2.2 µF, 10 V, +/- 10%, X7R, 0805"
C15: "CAP, CERM, 1 µF, 16 V, +/- 10%, X7R, 0603"
C17: "CAP, CERM, 10 pF, 50 V, +/- 5%, C0G/NP0, 0402"
C18 C19: "CAP, CERM, 1 pF, 50 V, +/- 10%, C0G/NP0, 0402"
C21 C22: "CAP, CERM, 24 pF, 50 V, +/- 5%, C0G/NP0, 0402"
C33 C34: "CAP, CERM, 20 pF, 50 V, +/- 5%, C0G/NP0, 0603"
C38 C40: "CAP, CERM, 4.7 µF, 6.3 V, +/- 20%, X5R, 0402"
C41: "CAP, CERM, 4700 pF, 25 V, +/- 10%, X7R, 0402"
D1: "Diode, TVS, Bi, 5 V, 400 W, SMA"
D4 D6 D7 D8 D9 D10 D11 D12 D13 D15 D16: "ESD in 0402 Package with 10 pF Capacitance and 6 V Breakdown, 1 Channel, -40 to +125 degC, 2-pin X2SON (DPY), Green (RoHS & no Sb/Br)"
D5: "LED, Green, SMD"
D14: "Diode, TVS, Bi, 24 V, 350 W, SOT-23"
E1: "ANT BLUETOOTH W-LAN ZIGBEE WIMAX, SMD"
FID1 FID2 FID3: "Fiducial mark.  There is nothing to buy or mount."
H1 H2 H3 H4: "Machine Screw, Round, #4-40 x 1/4, Nylon, Philips panhead"
H5 H6 H7 H8: "Standoff, Hex, 0.5\"L #4-40 Nylon"
J1: "Connector, Receptacle, Micro-USB Type B, R/A, Bottom Mount SMT"
J2: "Header, 100mil, 2x1, Tin, TH"
J3: "Header, 100mil, 7x2, Tin, TH"
J4: "Coaxial Connectors with Switch, 50 Ohm, SMD"
J5 J10: "Header, 100mil, 3x1, Gold, TH"
J6: "SMA Straight PCB Socket Die Cast, 50 Ohm, TH"
J8: "D-Sub-9, 11Pos, Female, TH"
J11: "Header, 100mil, 2x1, Gold, TH"
L3: "Inductor, Multilayer, Air Core, 3.6 nH, 0.3 A, 0.18 ohm, SMD"
L4: "Inductor, Film, 3.6 nH, 0.17 A, 0.5 ohm, SMD"
Logo1: library part TI_Logo, "Texas Instrument Corporate Signature"
Logo2: library part Pb-Free
Logo3: library part IEC_Caution, "IEC 61010-1 Caution Warning"
Logo4: library part FCC_disclaimer, "FCC_disclaimer"
R1: "RES, 0, 5%, 0.75 W, 2010"
R2 R12 R13 R14 R15 R17: "RES, 0, 5%, 0.063 W, 0402"
R11: "RES, 10.0 k, 1%, 0.063 W, 0402"
R16: "RES, 200 k, 1%, 0.063 W, 0402"
R18 R19: "RES, 60.4, 1%, 0.1 W, 0603"
R20 R22 R23 R24 R25 R26 R29 R30: "RES, 100 k, 1%, 0.063 W, 0402"
R21: "RES, 402, 1%, 0.063 W, 0402"
R27: "RES, 2.67 k, 1%, 0.063 W, 0402"
R28: "RES, 270, 5%, 0.063 W, 0402"
S1 S2: "SWITCH TACTILE SPST-NO 0.05A 12V"
SH-J2 SH-J11: "Shunt, 2mm, Gold plated, Black"
TP1 TP2 TP3: "Test Point, Miniature, Red, TH"
TP4 TP5: "Test Point, Multipurpose, Grey, TH"
TP6 TP7 TP8 TP9 TP10: library part PogoPad, "Pad for Pogo Pin Connector"
U1: "Single Output LDO, 1 A, Fixed 3.3 V Output, 2 to 5.5 V Input, 4-pin SOT-223 (DCY), -40 to 125 degC, Green (RoHS & no Sb/Br)"
U2: "DUAL CHANNEL HIGH SPEED ESD PROTECTION DEVICE, DRL0005A"
U3: "Tiva C Series Microcontroller, PM0064A"
U4: "SimpleLink™ Certified Wi-Fi® Network Processor Internet-of-Things Module Solution for MCU Applications, MOB0063A"
U5: "CAN Transceiver with Fast Loop Times for Highly Loaded Networks, 85 mA, 5 V, -40 to 125 degC, 8-pin SOIC (D), Green (RoHS & no Sb/Br)"
Y1: "Crystal, 32.768kHz, 12.5pF, SMD"
Y2: "Crystal, 16 MHz, 18 pF, SMD"
ZZ1 ZZ2 ZZ3 ZZ4: library part AssemblyNote

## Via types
v1: diameter 24, hole 12, Top Layer to Bottom Layer, tented both sides, 294 vias
v2: diameter 19.68, hole 7.87, Top Layer to Bottom Layer, tented both sides, 36 vias
v3: diameter 34, hole 16, Top Layer to Bottom Layer, tented both sides, 2 vias

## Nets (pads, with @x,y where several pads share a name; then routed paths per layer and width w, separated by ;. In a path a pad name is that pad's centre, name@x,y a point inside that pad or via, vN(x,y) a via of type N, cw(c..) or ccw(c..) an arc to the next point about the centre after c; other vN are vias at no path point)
3V3: C6.1 C7.1 C8.1 C9.1 C10.1 C11.1 C36.1 C38.1 C39.1 C40.1 D5.1 R1.2 R11.2 R14.2 R16.1 R20.2 R22.2 R24.2 R28.2 U3.2 U3.11 U3.26 U3.37 U3.42 U3.54 U4.36 U4.37 U4.40 U5.5 | length 2304.6
  Top Layer w10: R1.2@661.55,1840 662.55,1841 v1(714,1841) ; R1.2@662.55,1801 v1(714,1801) ; R1.2@662.55,1881 v1(714,1881) ; v1(995,1260) 996.38,1258.62 C7.1@1028,1258.62 1095.15,1258.62 1118,1281.47 U3.42@1199.5,1281.47 ; v1(1060,1340) 1058.62,1341.38 C6.1@1058.62,1370 1100,1370 1109.9,1379.9 U3.37@1199.5,1379.9 ; v1@1111,1634 R16.1@1162.38,1634 ; v1(1285,2935) R22.2@1335.38,2935 ; C8.1@1323.62,1000 1326.49,1002.87 1348,1002.87 1368.79,1023.65 U3.54@1368.79,1092.5 1368.79,1158.79 v1(1370,1160) ; v1(1325,1625) 1325.38,1625.38 C11.1@1363,1625.38 1363,1597 1387.57,1572.43 1387.57,1530.41 U3.26@1388.47,1529.5 ; v1@1471.38,751.38 C36.1@1510,751.38 ; C36.1@1505,756.38 1506.9,754.48 U5.5@1586.35,754.48 ; v1@1602,1707 R24.2@1602,1751.38 ; U3.2@1636.5,1183.05 1763.33,1183.05 C9.1@1765,1181.38 v1@1818.62,1181.38 ; U3.11@1636.5,1360.21 1759.17,1360.21 C10.1@1768,1351.38 1821.38,1351.38 1840,1370 v1@1840,1400 ; v1@2080,1970 R28.2@2131.38,1970 ; v1@2172,737 R11.2@2172,777.38 ; R14.2@2608.13,1082 v1@2648,1082
  Top Layer w20: v1(609.68,2175.32) D5.1@609.68,2222.47 ; v1(850,2365) R20.2@904.38,2365 ; v1@1236.62,2653.38 C38.1@1236.62,2620 1275,2620 1302,2593 U4.40@1302,2530.93 ; v3(1433,2690) 1433,2688 1452,2669 U4.37@1452,2530.93 ; U4.36@1502,2530.93 1502,2664 v3(1518,2680)
  other v1: 2170,735 1470,750 2650,1084 1815,1179 1840,1404 1110,1634 1600,1709 758.56,1801 758.56,1841 758.56,1881 2080,1969 1235,2655
3V3_OUT: C4.1 C5.1 R1.1 TP3.1 U1.2 U1.4 | length 719.6
  Top Layer w20: TP3.1@402,2097 431.45,2067.55 ; U1.2@507,1135.94 U1.4@507,1364.29 513.96,1371.25 513.96,1530.12 513.96,1668.12 513.96,1811.04
5V: C2.1 C3.1 J2.2 R2.2 TP2.1 U1.3
5V_CAN: C35.1 R2.1 U5.3 | length 1094.6
  Top Layer w10: R2.1@744.62,710 v1(790,710) ; v1(1596,1017) C35.1@1633.38,1017 1633.38,942.49 U5.3@1636.35,939.52
  Bottom Layer w10: v1(790,710) 1040,710 1205,875 1454,875 v1(1596,1017)
ANT_LEG: C19.1 L4.1 R15.1 | length 330.3
  Top Layer w18: R15.1@1752,2780.69 1752,2837.6 L4.1@1752,3111
CAN_N: D14.1 J8.2 R19.2 U5.6 | length 652.8
  Top Layer w8.5: R19.2@1634.5,654 R19.2@1644.6,664.1
  Top Layer w12: J8.2@1497.13,460.63 1497.13,485.13 1578,566 1626,566 1645,585 1645,643.5 R19.2@1634.5,654 ; U5.6@1636.35,754.48 1636.35,712.83 1644.6,704.58 R19.2@1644.6,664.1
  Bottom Layer w8.5: J8.2@1497.13,460.63 1517.56,481.07
  Bottom Layer w12: 1517.56,481.07 1517.56,586.44 1547.12,616 1595.29,616 1607.54,628.24 D14.1@1623.6,628.24
CAN_P: D14.2 J8.7 R18.2 U5.7 | length 865.9
  Top Layer w12: J8.7@1551.06,360.63 1551.06,486.74 1593.33,529 1641.33,529 1682,569.67 1682,645.5 R18.2@1691.5,655 ; R18.2@1678.1,655 1678.1,704.58 1686.35,712.83 U5.7@1686.35,754.48
  Bottom Layer w12: J8.7@1551.06,360.63 1551.06,572.56 1561,582.5 1636.6,582.5 1682.34,628.24 D14.2@1698.4,628.24
CAN_RX: U3.59 U5.4 | length 252.1
  Top Layer w10: U3.59@1467.21,1092.5 1467.21,1022.79 1492,998 1577,998 1586.35,988.65 U5.4@1586.35,939.52
CAN_TX: U3.60 U5.1 | length 423.8
  Top Layer w10: U3.60@1486.9,1092.5 1486.9,1038.1 1500,1025 1556.01,1025.31 1584.83,1054.13 1715.87,1054.13 1736.35,1033.65 U5.1@1736.35,939.52
CC_HIB: U3.23 U4.4 | length 466.5
  Top Layer w10: U4.4@1302,1897.07 1302,1836 1347,1791 1413,1791 1447.53,1756.47 U3.23@1447.53,1529.5
CC_INT: U3.24 U4.11 | length 970.6
  Top Layer w10: U3.24@1427.84,1529.5 1427.84,1471.16 1446.84,1452.16 v1(1461,1452.16) ; v1(1652,1844) U4.11@1652,1897.07
  Bottom Layer w10: v1(1461,1452.16) 1461,1668.98 1313.63,1816.35 1313.63,1851.79 1332.83,1870.99 1378.62,1870.99 1405.61,1844 v1(1652,1844)
CC_RF_OUT: J4.1 U4.31 | length 79.3
  Top Layer w18: U4.31@1752,2530.93 J4.1@1752,2610.2
CC_RX: D9.1 J10.2 R20.1 U4.46 | length 953.2
  Top Layer w10: v1@951.62,2403.62 R20.1@951.62,2365 952.62,2364 U4.46@1151.02,2364
  Bottom Layer w10: J10.2@878,3092 878,3054 890,3042 D9.1@890,3019 ; D9.1@893.32,3010 893.32,2451.68 941,2404 v1(952,2404)
CC_TX: D8.1 J10.1 U4.47 | length 1120
  Top Layer w10: v1(952,2314) U4.47@1151.02,2314
  Bottom Layer w10: J10.1@778,3092 778,3049 792.32,3034.69 D8.1@792.32,3010 792.32,2352.68 831,2314 v1(952,2314)
CS_CC: U3.20 U4.8 | length 369.5
  Top Layer w10: U4.8@1502,1897.07 1506.58,1892.49 U3.20@1506.58,1529.5
CTS: TP6.1 U4.51 | length 269.4
  Top Layer w10: TP6.1@882,2115 883,2114 U4.51@1151.02,2114
FORCE_AP: R24.1 U4.10 | length 98.4
  Top Layer w10: R24.1@1602,1798.62 U4.10@1602,1897.07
